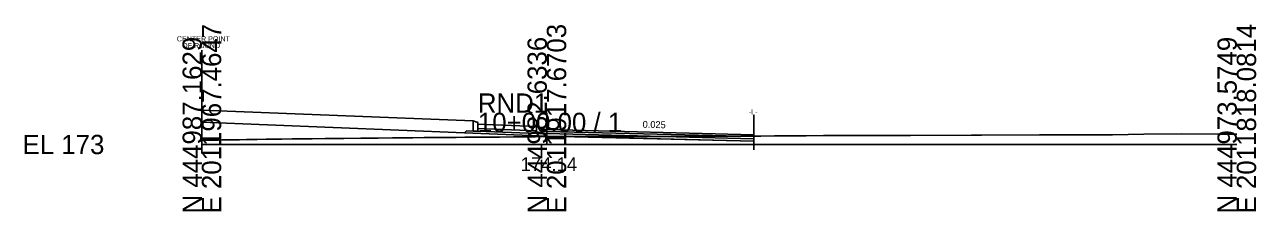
# Model space of a CAD drawing. Extents: x -26 to 153, y -10 to 6017.
# Drawn here: x -25.7 to 152.8, y -9.7 to 17.4 of the extents above; entities that cross this region are included whole.
import ezdxf

# ---------------------------------------------------------------- set-up
doc = ezdxf.new("R2010")
doc.units = 0
for name, color, linetype in [('Exist Cross Section Cell', 7, 'Continuous'), ('Exist XS Ground Line', 7, 'Continuous'), ('Prop CMT Conc Surface', 7, 'Continuous'), ('Prop CMT Concrete Structures', 7, 'Continuous'), ('Prop CMT Pvmt Course 1', 7, 'Continuous'), ('Prop CMT Pvmt Course 1 CG', 7, 'Continuous'), ('Prop CMT Pvmt Course 2', 7, 'Continuous'), ('Prop CMT Pvmt Course 3', 7, 'Continuous'), ('Prop CMT Pvmt Surface', 7, 'Continuous'), ('Prop CMT Shear Line', 7, 'Continuous'), ('Prop CMT Shear Line Text', 7, 'Continuous'), ('Prop CMT Slope Grass', 7, 'Continuous'), ('Prop CMT Subgrade Earthwork', 7, 'Continuous'), ('Prop XS Earthwork Shape', 7, 'Continuous'), ('Prop XS SE Text', 7, 'Continuous')]:
    doc.layers.add(name, color=color, linetype=linetype)

msp = doc.modelspace()

# ---------------------------------------------------------------- linework, layer by layer
at = {"layer": 'Exist Cross Section Cell'}
for p, q in [((50, 0), (50, 4.6)), ((0, 0), (50, 0)), ((50, 0), (150, 0))]:
    msp.add_line(p, q, dxfattribs=at)
at = {"layer": 'Exist XS Ground Line'}
msp.add_lwpolyline([(0, 0.62), (0.45, 0.63), (2.34, 0.65), (2.96, 0.66), (4.64, 0.68), (5.47, 0.69), (6.46, 0.71), (8.03, 0.73), (9.33, 0.75), (10.55, 0.76), (11.57, 0.78), (13.08, 0.8), (13.79, 0.81), (15.6, 0.83), (15.96, 0.83), (17.89, 0.86), (18.45, 0.87), (20.57, 0.89), (23.04, 0.91), (25.54, 0.94), (27.63, 0.95), (28.06, 0.96), (28.58, 0.96), (30.57, 0.98), (32.24, 1), (33.09, 1), (34.56, 1.01), (35.59, 1.02), (36.86, 1.03), (38.1, 1.04), (39.59, 1.06), (40.61, 1.06), (42.38, 1.08), (43.12, 1.08), (45.16, 1.1), (45.64, 1.1), (48.32, 1.13), (50, 1.14), (50.32, 1.14), (50.66, 1.14), (53.43, 1.16), (55.68, 1.17), (57.56, 1.17), (58.18, 1.17), (59.87, 1.17), (60.71, 1.17), (62.18, 1.17), (63.2, 1.17), (64.45, 1.17), (65.73, 1.18), (66.8, 1.18), (68.22, 1.18), (69.97, 1.18), (70.74, 1.18), (72.73, 1.18), (73.24, 1.18), (73.66, 1.18), (75.77, 1.19), (78.27, 1.21), (80.71, 1.22), (81.03, 1.22), (82.98, 1.24), (83.82, 1.25), (85.3, 1.26), (86.68, 1.27), (87.58, 1.27), (90.08, 1.29), (91.97, 1.3), (92.49, 1.3), (94.15, 1.31), (94.71, 1.31), (95.32, 1.31), (96.34, 1.31), (97.23, 1.31), (98.18, 1.31), (98.59, 1.31), (100.62, 1.31), (102.73, 1.31), (111.54, 1.35), (113, 1.36), (121.41, 1.38), (124.58, 1.4), (132, 1.41), (136.51, 1.51), (142.02, 1.53), (147.63, 1.51), (150, 1.51)], dxfattribs=at)
at = {"layer": 'Prop CMT Conc Surface'}
for points in [[(40, 3.11), (39.96, 3.22), (39.85, 3.26), (39.34, 3.45)], [(40, 2.95), (40, 3.11)], [(50, 2.15), (49.25, 2.17), (49.25, 2.34), (48.5, 2.59)]]:
    msp.add_lwpolyline(points, dxfattribs=at)
at = {"layer": 'Prop CMT Concrete Structures'}
for points in [[(40, 3.11), (39.96, 3.22), (39.85, 3.26), (39.34, 3.45)], [(39.34, 3.45), (39.34, 1.95)], [(39.34, 1.95), (40, 1.95)], [(40, 2.95), (40, 3.11)], [(40, 1.95), (40, 2.95)], [(40, 2.95), (40, 2.36)], [(48.5, 2.59), (40, 2.93)], [(40, 2.34), (48.5, 2)], [(50, 2.15), (49.25, 2.17), (49.25, 2.34), (48.5, 2.59)], [(48.5, 2.59), (48.5, 1.6)], [(48.5, 2), (48.5, 2.59)], [(50, 1.57), (50, 2.15)], [(48.5, 1.6), (50, 1.57)]]:
    msp.add_lwpolyline(points, dxfattribs=at)
at = {"layer": 'Prop CMT Pvmt Course 1'}
for points in [[(50, 2.15), (80, 1.4)], [(50, 1.9), (50, 2.15)], [(80, 1.15), (50, 1.9)], [(80, 1.4), (80, 1.15)]]:
    msp.add_lwpolyline(points, dxfattribs=at)
msp.add_lwpolyline([(50, 1.9), (50, 2.02), (50, 2.02), (50, 1.9)], close=True, dxfattribs=at)
at = {"layer": 'Prop CMT Pvmt Course 1 CG'}
for points in [[(50, 1.23), (50, 1.57)], [(80, 0.48), (80, 0.81)]]:
    msp.add_lwpolyline(points, dxfattribs=at)
at = {"layer": 'Prop CMT Pvmt Course 2'}
for points in [[(50, 1.57), (50, 1.9)], [(50, 1.9), (80, 1.15)], [(80, 0.81), (50, 1.57)], [(80, 1.15), (80, 0.81)]]:
    msp.add_lwpolyline(points, dxfattribs=at)
at = {"layer": 'Prop CMT Pvmt Course 3'}
for points in [[(40, 1.95), (48.5, 1.6)], [(50, 1.57), (80, 0.81)], [(50, 1.23), (50, 1.57)], [(80, 0.48), (50, 1.23)], [(80, 0.81), (80, 0.48)]]:
    msp.add_lwpolyline(points, dxfattribs=at)
at = {"layer": 'Prop CMT Pvmt Surface'}
msp.add_lwpolyline([(50, 2.15), (80, 1.4)], dxfattribs=at)
at = {"layer": 'Prop CMT Shear Line'}
for p, q in [((0, -1.31), (0, 13.69)), ((80, -0.78), (80, 4.24))]:
    msp.add_line(p, q, dxfattribs=at)
at = {"layer": 'Prop CMT Slope Grass'}
for p, q in [((39.34, 3.43), (0, 5)), ((38.06, 1.71), (0, 3.23))]:
    msp.add_line(p, q, dxfattribs=at)
at = {"layer": 'Prop CMT Subgrade Earthwork'}
for p, q in [((0, 5), (0, 0.62)), ((38.34, 1.99), (38.06, 1.71)), ((80, 1.4), (80, 1.21)), ((80, 0.48), (80, 1.21))]:
    msp.add_line(p, q, dxfattribs=at)
for points in [[(38.34, 1.99), (39.34, 1.95)], [(38.06, 1.71), (50, 1.23)], [(50, 1.23), (80, 0.48)]]:
    msp.add_lwpolyline(points, dxfattribs=at)
at = {"layer": 'Prop XS Earthwork Shape'}
for points in [[(50, 1.14), (50.32, 1.14), (50.66, 1.14), (52.94, 1.16), (50, 1.23), (38.06, 1.71), (0, 3.23), (0, 0.62), (0.45, 0.63), (2.34, 0.65), (2.96, 0.66), (4.64, 0.68), (5.47, 0.69), (6.46, 0.71), (8.03, 0.73), (9.33, 0.75), (10.55, 0.76), (11.57, 0.78), (13.08, 0.8), (13.79, 0.81), (15.6, 0.83), (15.96, 0.83), (17.89, 0.86), (18.45, 0.87), (20.57, 0.89), (23.04, 0.91), (25.54, 0.94), (27.63, 0.95), (28.06, 0.96), (28.58, 0.96), (30.57, 0.98), (32.24, 1), (33.09, 1), (34.56, 1.01), (35.59, 1.02), (36.86, 1.03), (38.1, 1.04), (39.59, 1.06), (40.61, 1.06), (42.38, 1.08), (43.12, 1.08), (45.16, 1.1), (45.64, 1.1), (48.32, 1.13)], [(75.77, 1.19), (78.27, 1.21), (80, 1.21), (80, 0.48), (52.94, 1.16), (53.43, 1.16), (55.68, 1.17), (57.56, 1.17), (58.18, 1.17), (59.87, 1.17), (60.71, 1.17), (62.18, 1.17), (63.2, 1.17), (64.45, 1.17), (65.73, 1.18), (66.8, 1.18), (68.22, 1.18), (69.97, 1.18), (70.74, 1.18), (72.73, 1.18), (73.24, 1.18), (73.66, 1.18)]]:
    msp.add_lwpolyline(points, close=True, dxfattribs=at)

# ---------------------------------------------------------------- texts
at = {"layer": 'Exist Cross Section Cell'}
for s, p in [('E 2011967.4647', (2.8, -10)), ('E 2011917.6703', (52.8, -10)), ('E 2011818.0814', (152.8, -10)), ('N 444987.1629', (0, -10)), ('N 444982.6336', (50, -10)), ('N 444973.5749', (150, -10))]:
    msp.add_text(s, height=2.8, rotation=90, dxfattribs=at).set_placement(p)
for s, p in [('RND1', (40, 4.6)), ('10+00.00 / 1', (40, 1.8)), ('EL 173', (-26, -1.4))]:
    msp.add_text(s, height=2.8, dxfattribs=at).set_placement(p)
at = {"layer": 'Exist XS Ground Line'}
msp.add_text('174.14', height=2, dxfattribs=at).set_placement((46.2, -3.86))
at = {"layer": 'Prop CMT Shear Line Text'}
for s, p in [('CENTER POINT', (-3.64, 14.94)), ('OF ROUND', (-2.88, 13.97)), ('-L-', (79.27, 4.35))]:
    msp.add_text(s, height=0.75, dxfattribs=at).set_placement(p)
at = {"layer": 'Prop XS SE Text'}
msp.add_text('0.025', height=1, rotation=358.5613, dxfattribs=at).set_placement((63.87, 2.43))

doc.saveas('drawing.dxf')
